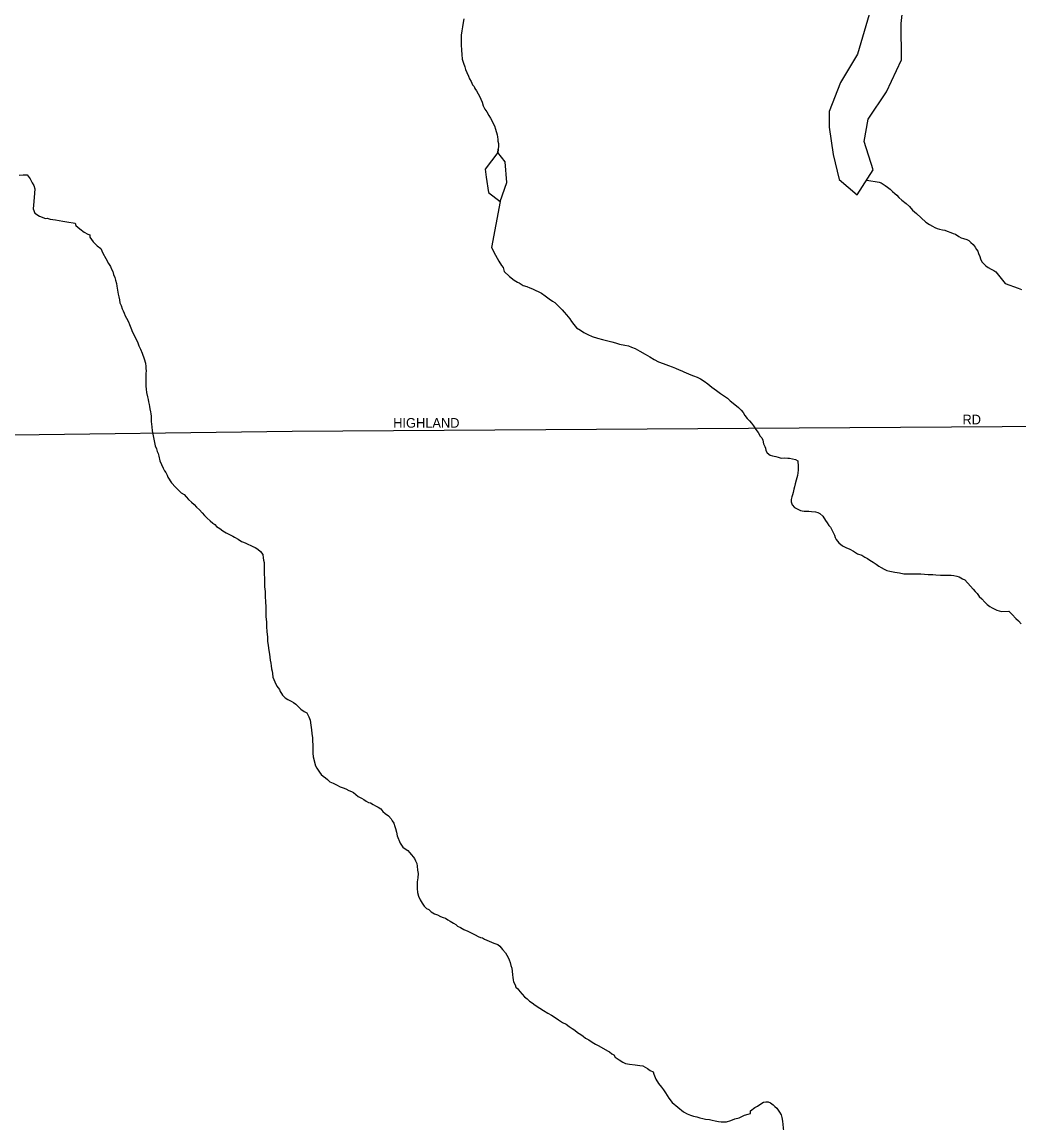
# Model space of a CAD drawing. Extents: x 2139079 to 2262683, y 1235796 to 1334992.
# Drawn here: x 2237265 to 2242458, y 1292167 to 1297901 of the extents above; entities that cross this region are included whole.
import ezdxf

# ---------------------------------------------------------------- set-up
doc = ezdxf.new("R2010")
doc.units = 0
for name, color, linetype in [('GM_X_City_Street', 7, 'Continuous'), ('GM_X_City_Street_Text', 7, 'Continuous'), ('GM_X_Minor_Lake', 7, 'Continuous'), ('GM_X_Minor_River', 7, 'Continuous')]:
    doc.layers.add(name, color=color, linetype=linetype)

msp = doc.modelspace()

# ---------------------------------------------------------------- linework, layer by layer
at = {"layer": 'GM_X_City_Street'}
msp.add_lwpolyline([(2234791, 1297589.9), (2234951.4, 1297371.4), (2235265.9, 1296994), (2235724.2, 1296409.4), (2235847, 1296237.8), (2235885.9, 1296204.7), (2235972.3, 1296120.6), (2236081, 1296029), (2236197.2, 1295955.7), (2236392.2, 1295856.3), (2236499.6, 1295814.9), (2236606.8, 1295779.6), (2236801.9, 1295756.5), (2237088.8, 1295749.8), (2238672.4, 1295770.7), (2243162.7, 1295800.6)], dxfattribs=at)
at = {"layer": 'GM_X_Minor_Lake'}
for points in [[(2241749.6, 1298177), (2241695, 1297999.1), (2241616.1, 1297734.2), (2241528.8, 1297585.8), (2241469.6, 1297436), (2241469.3, 1297353.6), (2241490.2, 1297211.3), (2241521, 1297081.2), (2241615, 1297000.7), (2241698.7, 1297130.9), (2241651.5, 1297278.7), (2241673.2, 1297395.7), (2241768.7, 1297538.2), (2241845.6, 1297704.5), (2241843.8, 1297893.4), (2241867.6, 1298100.9), (2241849.6, 1298195), (2241749.6, 1298177)], [(2239743, 1297221.7), (2239676.5, 1297134), (2239682.8, 1297093.4)], [(2239682.8, 1297093.4), (2239695, 1297013.8), (2239756.2, 1296966.7), (2239790.4, 1297065.8), (2239782.2, 1297172.2), (2239743, 1297221.7)]]:
    msp.add_lwpolyline(points, dxfattribs=at)
at = {"layer": 'GM_X_Minor_River'}
for points in [[(2239566.1, 1297917.7), (2239562.4, 1297899.5), (2239558.9, 1297875.3), (2239555.3, 1297855.2), (2239551.8, 1297833), (2239552.3, 1297808.9), (2239552.8, 1297782.8), (2239553.4, 1297754.6), (2239555.8, 1297732.6), (2239558.3, 1297708.5), (2239564.8, 1297686.5), (2239571.2, 1297668.6), (2239575.5, 1297654.6), (2239581.8, 1297638.6), (2239590.3, 1297618.7), (2239596.6, 1297604.7), (2239604.9, 1297590.8), (2239611.3, 1297574.9), (2239619.5, 1297565), (2239623.7, 1297555), (2239632, 1297543.1), (2239640.4, 1297527.2), (2239648.6, 1297515.3), (2239655, 1297499.3), (2239661.3, 1297483.4), (2239667.7, 1297465.4), (2239676.1, 1297447.5), (2239686.4, 1297433.6), (2239696.9, 1297413.7), (2239705.2, 1297399.8), (2239711.5, 1297387.9), (2239717.7, 1297375.9), (2239726.1, 1297360), (2239730.4, 1297344), (2239739.1, 1297314.1), (2239741.3, 1297304.1), (2239743.6, 1297290), (2239743.8, 1297280), (2239746.1, 1297268), (2239746.3, 1297253.9), (2239743, 1297221.7), (2239744.6, 1297239.8)], [(2237249.4, 1297103.1), (2237271.4, 1297105.6), (2237291.5, 1297106), (2237308, 1297084.2), (2237318.4, 1297064.3), (2237326.7, 1297050.4)], [(2241665.5, 1297077.7), (2241730.1, 1297067.2), (2241740.3, 1297063.4), (2241750.4, 1297057.5), (2241760.6, 1297049.7), (2241772.8, 1297041.9), (2241787.1, 1297030.1), (2241799.4, 1297018.3), (2241811.7, 1297008.5), (2241821.9, 1296998.6), (2241832.2, 1296986.8), (2241848.5, 1296973), (2241871, 1296955.4), (2241887.4, 1296939.6), (2241903.8, 1296921.8), (2241924.2, 1296904.1), (2241973.4, 1296858.9), (2241991.7, 1296847.2), (2242007.9, 1296837.4), (2242020.1, 1296831.6), (2242032.3, 1296825.8), (2242044.4, 1296822.1), (2242060.5, 1296818.4), (2242072.6, 1296816.6), (2242084.8, 1296812.8), (2242103, 1296805.1), (2242115.1, 1296799.3), (2242127.3, 1296795.5), (2242145.6, 1296783.8), (2242157.7, 1296778), (2242169.9, 1296774.3), (2242186.1, 1296768.5), (2242196.2, 1296762.7), (2242206.5, 1296752.8), (2242218.7, 1296743.1), (2242229, 1296729.2), (2242237.3, 1296717.3), (2242243.5, 1296707.3), (2242247.8, 1296695.4), (2242254.1, 1296679.4), (2242258.4, 1296667.4), (2242264.8, 1296651.5), (2242275, 1296641.6), (2242285.2, 1296631.8), (2242297.5, 1296622), (2242313.7, 1296614.2), (2242327.9, 1296606.5), (2242338.1, 1296600.7), (2242386, 1296539.8)], [(2237326.7, 1297050.4), (2237331.1, 1297032.4), (2237328, 1296988.1), (2237324.8, 1296947.8), (2237323.2, 1296927.7), (2237331.7, 1296905.8), (2237356.1, 1296890.2), (2237386.5, 1296878.7), (2237396.5, 1296878.9), (2237410.7, 1296875.1), (2237438.8, 1296871.7), (2237477.1, 1296864.4), (2237509.4, 1296859), (2237531.6, 1296855.4), (2237541.6, 1296853.6), (2237545.9, 1296841.6), (2237566.3, 1296823.9), (2237588.8, 1296806.2), (2237607.1, 1296796.5), (2237617.2, 1296792.7), (2237617.4, 1296780.7), (2237636, 1296756.9), (2237656.5, 1296735.2), (2237674.9, 1296721.5), (2237685.4, 1296697.6), (2237702, 1296669.8), (2237714.6, 1296643.9), (2237725, 1296628), (2237731.3, 1296614.1), (2237737.5, 1296602.1), (2237741.9, 1296586.1), (2237748.2, 1296570.2), (2237752.5, 1296556.2), (2237756.9, 1296540.2), (2237759.2, 1296526.2), (2237766.1, 1296484.1), (2237768.3, 1296470.1), (2237772.7, 1296454.1), (2237775, 1296438.1), (2237781.3, 1296424.1), (2237785.7, 1296408.1), (2237791.9, 1296396.2), (2237796.2, 1296384.2), (2237802.5, 1296370.2), (2237808.8, 1296358.3), (2237819.2, 1296340.4), (2237825.5, 1296326.5), (2237831.9, 1296308.5), (2237840.4, 1296286.6), (2237850.8, 1296266.7), (2237857.2, 1296250.7), (2237865.5, 1296234.8), (2237874, 1296214.9), (2237882.4, 1296197), (2237890.8, 1296177), (2237901.5, 1296147.1), (2237907.9, 1296125.1), (2237910.3, 1296107.1), (2237910.5, 1296097), (2237910.8, 1296085), (2237909, 1296070.9), (2237909.4, 1296052.8), (2237909.9, 1296028.7), (2237910.4, 1296004.6), (2237910.7, 1295988.5), (2237913.1, 1295972.5), (2237917.6, 1295948.5), (2237921.9, 1295934.5), (2237924.1, 1295922.5), (2237926.4, 1295908.4), (2237928.6, 1295898.4), (2237930.9, 1295886.4), (2237933.2, 1295870.4), (2237935.4, 1295860.4), (2237937.7, 1295848.4), (2237938, 1295834.3), (2237938.3, 1295820.3), (2237938.5, 1295806.2), (2237940.8, 1295792.2), (2237943.3, 1295772.1), (2237945.6, 1295754.1), (2237958.9, 1295694.1), (2237965.3, 1295678.1), (2237969.6, 1295664.1), (2237973.8, 1295654.1), (2237978.1, 1295640.2), (2237982.6, 1295616.1), (2237991, 1295596.2), (2237999.4, 1295578.3), (2238007.7, 1295564.4), (2238014, 1295554.5), (2238020.3, 1295540.5), (2238024.5, 1295530.6), (2238043.2, 1295500.8), (2238063.7, 1295479.1), (2238080.1, 1295463.3), (2238094.4, 1295449.5), (2238108.7, 1295439.7), (2238119, 1295427.9), (2238131.3, 1295414.1), (2238147.7, 1295400.3)], [(2239756.2, 1296966.7), (2239710.9, 1296726.7), (2239731.8, 1296686.9), (2239748.6, 1296655.1), (2239763.1, 1296633.2), (2239771.3, 1296623.3), (2239775.8, 1296601.3), (2239804.4, 1296575.8), (2239828.9, 1296556.1), (2239845.2, 1296546.4), (2239855.3, 1296542.6), (2239875.6, 1296528.9), (2239893.8, 1296523.2), (2239910, 1296517.5), (2239924.2, 1296511.8), (2239970.8, 1296488.6), (2239989.2, 1296474.8), (2240011.6, 1296459.2), (2240027.9, 1296447.4), (2240040.1, 1296439.6), (2240058.5, 1296423.9), (2240066.7, 1296414), (2240079, 1296402.2), (2240089.3, 1296390.3), (2240101.6, 1296376.5), (2240109.9, 1296366.6), (2240118.2, 1296354.7), (2240126.5, 1296340.8), (2240138.8, 1296325), (2240153.2, 1296309.2), (2240173.6, 1296295.5), (2240191.9, 1296283.8), (2240212.2, 1296274.2), (2240234.5, 1296262.5), (2240262.8, 1296255), (2240289, 1296247.5), (2240309.2, 1296241.9), (2240337.4, 1296236.4), (2240355.6, 1296230.7), (2240377.9, 1296223.1), (2240404.1, 1296217.6), (2240424.3, 1296214), (2240440.4, 1296208.2), (2240458.7, 1296200.6), (2240483, 1296187), (2240511.5, 1296171.4), (2240535.8, 1296157.8), (2240558.2, 1296144.2), (2240580.6, 1296130.6), (2240604.8, 1296123), (2240619, 1296117.2), (2240633.2, 1296111.5), (2240651.4, 1296105.8), (2240669.6, 1296098.1), (2240687.8, 1296090.4), (2240702, 1296084.7), (2240712.2, 1296078.9), (2240736.5, 1296069.3), (2240748.6, 1296063.5), (2240762.8, 1296057.7), (2240781, 1296052.1), (2240799.3, 1296042.4), (2240817.6, 1296030.7), (2240837.9, 1296017), (2240858.4, 1295999.3), (2240882.8, 1295981.7), (2240903.2, 1295966), (2240923.6, 1295952.3), (2240939.9, 1295942.6), (2240954.2, 1295928.8), (2240978.7, 1295909.2), (2240997.1, 1295893.5), (2241011.4, 1295879.7), (2241021.7, 1295867.8), (2241030.1, 1295851.9), (2241042.4, 1295836.1), (2241054.7, 1295824.2), (2241065, 1295812.4), (2241075.3, 1295798.5), (2241087.8, 1295778.7), (2241100.2, 1295762.8), (2241110.6, 1295744.9), (2241118.8, 1295735.1), (2241123.1, 1295723.1), (2241127.4, 1295705.1), (2241133.8, 1295691.1), (2241138, 1295681.2), (2241140.2, 1295669.2), (2241146.5, 1295657.2), (2241162.8, 1295645.5), (2241174.9, 1295641.7), (2241191.1, 1295638), (2241203.2, 1295634.2), (2241219.3, 1295630.5), (2241235.4, 1295630.8), (2241253.5, 1295629.1), (2241263.5, 1295629.3), (2241293.8, 1295621.9), (2241306, 1295616.1), (2241308.6, 1295586), (2241307, 1295567.9)], [(2242386, 1296539.8), (2242453.8, 1296514.2), (2242471.9, 1296508.4)], [(2241307, 1295567.9), (2241303.5, 1295539.7), (2241298, 1295515.5), (2241292.4, 1295495.3), (2241288.7, 1295481.1), (2241284.9, 1295469), (2241281.2, 1295450.8), (2241277.5, 1295438.7), (2241275.7, 1295428.6), (2241271.9, 1295414.5), (2241272.2, 1295402.4), (2241276.5, 1295386.4), (2241288.9, 1295372.6), (2241303.1, 1295364.9), (2241319.3, 1295357.1), (2241329.4, 1295355.3), (2241339.5, 1295353.5), (2241349.5, 1295353.7), (2241363.5, 1295354), (2241377.6, 1295352.2), (2241397.7, 1295350.6), (2241409.9, 1295346.8), (2241420, 1295341), (2241436.4, 1295327.2), (2241450.9, 1295305.4), (2241459.1, 1295293.5), (2241467.5, 1295279.6), (2241475.7, 1295269.8), (2241496.6, 1295227.9), (2241500.9, 1295216), (2241505.1, 1295206), (2241519.5, 1295188.2), (2241537.9, 1295172.5), (2241556.2, 1295164.8), (2241576.4, 1295155.1), (2241596.7, 1295145.5), (2241617.1, 1295131.8), (2241639.3, 1295124.2), (2241655.6, 1295114.5), (2241669.8, 1295106.7), (2241682, 1295098.9), (2241698.3, 1295087.2), (2241714.6, 1295077.4), (2241728.8, 1295067.7), (2241741, 1295059.9), (2241755.3, 1295052.1), (2241769.5, 1295044.3), (2241785.6, 1295040.6), (2241811.8, 1295035.1), (2241836, 1295031.6), (2241858.2, 1295028), (2241884.3, 1295026.5), (2241910.4, 1295027), (2241928.5, 1295027.3), (2241946.5, 1295027.7), (2241966.6, 1295026.1), (2241984.7, 1295024.4), (2241996.8, 1295024.6), (2242008.9, 1295022.9), (2242025, 1295021.2), (2242049.1, 1295019.6), (2242065.2, 1295019.9), (2242085.2, 1295020.3), (2242105.3, 1295020.7), (2242119.4, 1295019), (2242133.5, 1295015.2), (2242145.7, 1295011.4), (2242163.9, 1295001.8), (2242176.1, 1294996), (2242204.9, 1294962.4), (2242219.3, 1294946.6), (2242229.6, 1294934.7), (2242239.8, 1294924.8), (2242250.2, 1294909), (2242264.5, 1294897.2), (2242280.9, 1294879.4), (2242293.2, 1294867.6), (2242305.4, 1294857.8), (2242317.6, 1294850), (2242342, 1294838.4), (2242354.1, 1294834.6), (2242366.2, 1294830.8), (2242404.9, 1294833.2)], [(2238147.7, 1295400.3), (2238161.9, 1295388.5), (2238174.3, 1295374.7), (2238188.6, 1295360.9), (2238203, 1295345.1), (2238215.3, 1295331.3), (2238229.7, 1295317.5), (2238244, 1295303.7), (2238258.3, 1295291.9), (2238268.5, 1295284.1), (2238278.7, 1295274.2), (2238295.1, 1295262.5), (2238311.3, 1295250.8), (2238327.6, 1295241), (2238345.9, 1295231.3), (2238362.1, 1295223.6), (2238372.3, 1295217.8), (2238390.5, 1295208.1), (2238408.9, 1295196.4), (2238419, 1295192.6), (2238431.1, 1295186.8), (2238467.6, 1295169.4), (2238479.8, 1295163.6), (2238494, 1295155.8), (2238506.3, 1295144), (2238518.7, 1295128.2), (2238521.1, 1295110.1), (2238523.3, 1295098.1), (2238525.6, 1295086.1), (2238525.8, 1295074.1), (2238526.1, 1295060), (2238526.4, 1295043.9), (2238526.8, 1295025.8), (2238527.2, 1295003.8), (2238527.7, 1294983.7), (2238528.1, 1294959.6), (2238530.7, 1294935.5), (2238531.2, 1294909.4), (2238533.8, 1294881.3), (2238534.3, 1294855.2), (2238534.8, 1294829.1), (2238535.4, 1294803), (2238537.9, 1294776.9), (2238538.4, 1294750.8), (2238540.9, 1294726.7), (2238543.6, 1294696.6), (2238544, 1294674.5), (2238546.4, 1294656.5), (2238548.7, 1294640.5), (2238551, 1294628.5), (2238553.4, 1294608.4), (2238555.7, 1294592.4), (2238558, 1294578.4), (2238560.4, 1294562.3), (2238562.7, 1294548.3), (2238565, 1294532.3), (2238567.2, 1294520.3), (2238569.5, 1294508.3), (2238571.9, 1294488.2), (2238582.4, 1294464.3), (2238592.9, 1294442.4), (2238605.3, 1294424.6), (2238609.6, 1294414.6), (2238615.8, 1294404.7), (2238622, 1294394.8), (2238636.3, 1294381), (2238648.6, 1294373.2), (2238666.8, 1294363.5), (2238679, 1294357.7), (2238691.2, 1294347.9), (2238703.5, 1294336.1), (2238717.9, 1294322.3), (2238734.2, 1294310.5), (2238748.4, 1294302.8), (2238758.8, 1294282.9), (2238765.2, 1294264.9), (2238769.8, 1294238.9), (2238772.3, 1294214.8), (2238774.7, 1294194.8), (2238777.2, 1294172.7), (2238777.6, 1294152.6), (2238779.8, 1294140.6), (2238780, 1294130.6), (2238780.2, 1294120.5), (2238780.5, 1294106.5), (2238778.8, 1294092.4), (2238781.2, 1294074.3), (2238794.2, 1294026.4), (2238800.5, 1294014.4), (2238806.7, 1294004.5), (2238814.9, 1293994.6), (2238823.2, 1293982.7), (2238833.4, 1293972.9), (2238845.7, 1293965.1), (2238855.9, 1293955.2), (2238868.2, 1293943.4), (2238886.4, 1293937.7), (2238902.6, 1293928), (2238922.9, 1293918.3), (2238937.1, 1293912.6), (2238951.3, 1293906.8)], [(2242404.9, 1294833.2), (2242422.8, 1294814.6), (2242441.1, 1294794.7), (2242455.2, 1294782.8), (2242469.4, 1294766.9)], [(2238951.3, 1293906.8), (2238967.5, 1293899.1), (2238981.7, 1293893.4), (2238991.8, 1293887.5), (2239016.3, 1293867.9), (2239032.6, 1293858.2), (2239044.7, 1293852.4), (2239057, 1293842.6), (2239069.2, 1293836.8), (2239079.2, 1293835), (2239093.5, 1293825.2), (2239105.7, 1293819.4), (2239119.9, 1293811.7), (2239134.1, 1293803.9), (2239144.4, 1293790), (2239156.7, 1293778.2), (2239173, 1293766.5), (2239187.4, 1293750.7), (2239193.6, 1293740.8), (2239201.9, 1293728.9), (2239206.3, 1293710.8), (2239210.5, 1293700.9), (2239214.9, 1293680.9), (2239219.3, 1293662.9), (2239234.1, 1293625), (2239248.6, 1293603.2), (2239260.8, 1293595.4), (2239275.1, 1293585.6), (2239283.3, 1293575.7), (2239293.6, 1293563.9), (2239301.8, 1293554), (2239310.1, 1293544.1), (2239314.3, 1293532.1), (2239320.7, 1293518.2), (2239322.9, 1293504.2), (2239325.4, 1293484.1), (2239327.7, 1293466.1), (2239326.2, 1293443.9), (2239322.6, 1293423.8), (2239322.9, 1293407.7), (2239323.3, 1293387.6), (2239325.7, 1293367.6), (2239330.2, 1293347.6), (2239338.6, 1293329.7), (2239349, 1293311.8), (2239359.3, 1293295.9), (2239371.6, 1293284.1), (2239383.8, 1293278.3), (2239396.1, 1293266.5), (2239414.3, 1293256.8), (2239428.5, 1293251.1), (2239444.7, 1293243.3), (2239458.9, 1293237.6), (2239471, 1293233.8), (2239483.2, 1293226), (2239495.4, 1293218.2), (2239511.7, 1293208.4), (2239523.9, 1293200.6), (2239534.1, 1293192.8), (2239548.3, 1293185.1), (2239566.6, 1293175.4), (2239586.9, 1293165.7), (2239607.2, 1293156.1), (2239625.4, 1293146.4), (2239641.7, 1293138.6), (2239653.8, 1293132.8), (2239663.9, 1293131), (2239674.1, 1293125.2), (2239686.2, 1293119.4), (2239722.7, 1293104), (2239732.8, 1293100.2), (2239742.9, 1293096.4), (2239753.1, 1293088.6), (2239767.5, 1293070.8), (2239784, 1293053), (2239790.2, 1293041.1), (2239796.5, 1293029.1), (2239802.8, 1293017.2), (2239807.1, 1293003.2), (2239811.4, 1292987.2), (2239815.7, 1292973.2), (2239818.1, 1292957.2), (2239820.4, 1292939.2), (2239820.7, 1292925.1), (2239823, 1292913.1), (2239825.2, 1292903.1), (2239833.5, 1292887.2), (2239837.8, 1292875.2), (2239848, 1292865.4), (2239858.4, 1292851.5), (2239870.7, 1292837.7), (2239883, 1292823.9), (2239895.3, 1292814.1), (2239907.6, 1292802.2), (2239921.8, 1292792.5), (2239938.1, 1292780.7), (2239962.5, 1292765.1), (2239980.9, 1292753.4), (2240003.2, 1292739.8), (2240023.5, 1292728.1), (2240041.8, 1292716.4)], [(2240041.8, 1292716.4), (2240060.2, 1292704.7), (2240080.5, 1292691.1), (2240098.8, 1292681.4), (2240115.1, 1292669.6), (2240131.4, 1292659.9), (2240143.6, 1292650.1), (2240157.9, 1292638.3), (2240176.2, 1292628.6), (2240188.4, 1292618.8), (2240200.7, 1292609), (2240216.9, 1292599.3), (2240235.2, 1292587.6), (2240251.5, 1292577.8), (2240269.8, 1292568.2), (2240314.5, 1292542.9), (2240324.6, 1292537.1), (2240336.9, 1292527.3), (2240347, 1292521.4), (2240355.3, 1292509.6), (2240375.7, 1292495.9), (2240394, 1292484.2), (2240408.2, 1292476.4), (2240428.4, 1292472.8), (2240458.5, 1292469.3), (2240482.7, 1292465.8), (2240498.8, 1292464.1), (2240523.2, 1292450.5), (2240537.4, 1292440.8), (2240551.7, 1292433), (2240555.9, 1292421), (2240566.5, 1292395.1), (2240581, 1292373.3), (2240595.4, 1292353.5), (2240605.8, 1292339.6), (2240616.1, 1292323.7), (2240634.8, 1292296), (2240651.3, 1292274.2), (2240710.5, 1292225.1), (2240728.8, 1292215.4), (2240747, 1292207.7), (2240763.2, 1292202), (2240779.3, 1292198.3), (2240795.5, 1292194.6), (2240811.6, 1292190.9), (2240825.8, 1292187.2), (2240845.9, 1292185.5), (2240860, 1292181.8), (2240876.1, 1292178.1), (2240892.3, 1292174.4), (2240906.4, 1292172.6), (2240922.4, 1292172.9), (2240934.5, 1292173.2), (2240956.4, 1292179.6), (2240978.3, 1292188.1), (2241000.3, 1292194.6), (2241028.2, 1292207.1), (2241048.1, 1292213.6), (2241060.1, 1292215.8), (2241059.8, 1292229.8), (2241081.5, 1292248.4), (2241095.5, 1292254.7), (2241113.3, 1292267.1), (2241127.2, 1292275.4), (2241139.2, 1292277.6), (2241151.2, 1292277.8), (2241163.4, 1292272), (2241177.6, 1292262.3), (2241185.9, 1292252.4), (2241196.1, 1292244.5), (2241204.3, 1292234.7), (2241210.6, 1292222.7), (2241218.9, 1292208.8), (2241223.2, 1292194.8), (2241225.6, 1292176.8), (2241230.7, 1292124.7)]]:
    msp.add_lwpolyline(points, dxfattribs=at)

# ---------------------------------------------------------------- texts
at = {"layer": 'GM_X_City_Street_Text'}
for s, p in [('HIGHLAND', (2239198.1, 1295788.5)), ('RD', (2242163.7, 1295806))]:
    msp.add_text(s, height=50, rotation=0.00001, dxfattribs=at).set_placement(p)

doc.saveas('drawing.dxf')
